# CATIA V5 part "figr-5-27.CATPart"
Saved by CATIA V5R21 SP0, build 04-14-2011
Part number: Part1
Bounding box of the stored display mesh (mm): x -34.542 to 34.542, y -63.781 to 63.781, z 0 to 53
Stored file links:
  D:\CATIA V5R21 E-RESOURCES\CATIA-V5R21\catia-v5r21-prt\c05-catia-v5r20-prt\catia-v5r21-figr-5-27.CATPart
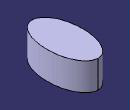
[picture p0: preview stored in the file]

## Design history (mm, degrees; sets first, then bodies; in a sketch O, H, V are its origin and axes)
Body1 (main body)
  Sketch1 on xy-plane, origin (0, 0, 0), H (1, 0, 0), V (0, 1, 0)
    line L1 (-75, 100) -> (75, 100)
    line L2 (75, 100) -> (75, -100)
    line L3 (75, -100) -> (-75, -100)
    line L4 (-75, -100) -> (-75, 100)
    axis line L5 (75, -100) -> (-75, 100)
    length L3 = 150
    length L2 = 200
    horizontal: L1 H, L3 H
    vertical: L2 V, L4 V
    midpoint: L5 O
  Pad1: profile Sketch1, direction (0, 0, 1), length 53
  Sketch2 on face of Pad1, origin (0, 0, 53), H (1, 0, 0), V (0, 1, 0)
    ellipse A1 centre (0, 0) semi-axes 63.781, 34.5424 rotation 270
    point P1 (0, -63.781)
    point P2 (34.5424, 0)
    coincidence: P1 V, P2 H, A1 P1, A1 P2
  Pocket1: profile Sketch2, direction (0, 0, -1), through (limit type 3), outer side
